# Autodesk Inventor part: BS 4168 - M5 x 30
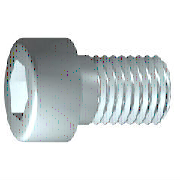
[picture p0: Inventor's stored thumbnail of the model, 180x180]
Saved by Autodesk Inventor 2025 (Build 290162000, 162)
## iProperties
Created: 2024-01
Part Number: BS 4168 - M5 x 30
Material: Acciaio, Dolce
Description: Vite con esagono incassato
Document SubType Name: Modeling
Standard: BS 4168
Designer: R5800u
Standards Organization: BSI
Language: it-IT
Size Designation: M5 x 30
Categories: <MemberInstance><Categories><Category DisplayName="Elementi di fissaggio" InternalName="e4da775c-781d-43d5-af7c-5136215cf5a6" Mnemonic="FSTN"><Category DisplayN
Density: 7.85 g/cm^3
Appearance: Semilucidato
IsCustomPart: 0
Author: R5800u
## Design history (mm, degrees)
workplane "Work Plane1"
fillet "Fillet2" dims "d30" = 0.1 (= R)
revolve "Corpo" stored, may be unused: angle "d10" = 90 deg
sketch "Schizzo2"
  geometry: L1 (0, -5.95)-(0, 5.95) reference; L2 (-5.95, 0)-(5.95, 0) reference; L3 (2.309, 0)-(1.155, -2); L4 (1.155, -2)-(-1.155, -2); L5 (-1.155, -2)-(-2.309, 0); L6 (-2.309, 0)-(-1.155, 2); L7 (-1.155, 2)-(1.155, 2); L8 (1.155, 2)-(2.309, 0); 2 further points
  constraints: 12 end point, 1 coincident, 1 horizontal alignment, 1 point on line, 12 other
extrude "Intaglio" join sketch "Schizzo2" stored distance "d11" = 10; taper "d12" = 0 deg
body "Solid1"
fillet "Raccordo1" dims "d17" = 0.5 (= RR)
feature "Filettatura" dims "d13" = 22 (= GEL), "d14" = 0
chamfer "Smusso1" distance "d15" = 0.49076 (= -0.5 x SPD + 0.5 x GD); stored, may be unused: second distance "d16" = 0.49076 (= GUL), angle "d27" = 45 deg
sketch "Schizzo1"
  geometry: L1 (-1.167, 0)-(30, 0); L2 (30, 0)-(30, 2.5); L3 (30, 2.5)-(8, 2.5); L4 (8, 2.5)-(7.509, 2.5); L5 (7.509, 2.5)-(0, 2.5); L6 (0, 2.5)-(0, 4.25); L7 (0, 4.25)-(-5, 4.25); L8 (-5, 4.25)-(-5, 2.309); L9 (-5, 2.309)-(-2.5, 2.309); L10 (-2.5, 2.309)-(-1.167, 0); L11 (-12, 0)-(37, 0) reference; L12 (0, -0.85)-(0, 5.1) reference; L13 (8, 2.5)-(0, 2.5)
  constraints: 22 end point, 6 parallel, 2 collinear, 2 perpendicular, 1 horizontal, 1 point on line
  dimensions: "d1" = 22 distance from line of L3.end L2 (= GEL); "d2" = 0.49086 distance of L4.end L3.end (computed from GAL); "d3" = 5 distance between parallel lines of L8 L6 (= KOH); "d4" = 2.5 distance of L8.end L9.end (= INTI); "d5" = 60 deg angle of L10 L1; "d6" = 5 diameter of L3 L1 (= GD); "d7" = 5 diameter of L5 L1 (= BDM); "d8" = 4.6188 diameter of L9 L1 (= 1.1547 x SW); "d9" = 8.5 diameter of L7 L1 (= KOD); "d26" = 30 distance between parallel lines of L12 L2 (= NLG)
other parameters: "GD" = 5 (= NND) [user parameter; used in 2 equation terms], "NLG" = 30 [user parameter; used in 1 equation term], "GEL" = 22 [user parameter; used in 2 equation terms], "KOD" = 8.5 [user parameter; used in 1 equation term], "KOH" = 5 (= NND) [user parameter; used in 1 equation term], "INTI" = 2.5 [user parameter; used in 1 equation term], "GAL" = 0.49076 (= 0.61345 x PTC) [user parameter; used in 1 equation term], "GUL" = 0.49076 (= 0.61345 x PTC) [user parameter; used in 1 equation term], "BDM" = 5 (= NND) [user parameter; used in 1 equation term], "SW" = 4 [user parameter; used in 2 equation terms], "RR" = 0.5 (= 0.1 x NND) [user parameter; used in 1 equation term], "SPD" = 4.01848 (= NND - 1.2269 x PTC) [user parameter; used in 1 equation term], "d19" = 0, "d28" = 0, "d29" = 0, "R" = 0.1 [user parameter; used in 1 equation term], "TOA" = 30 deg [user parameter], "GD1" = 4.01848 (= THREADDIA - 1.2269 x PTC) [user parameter], "THREADDIA" = 5 [user parameter; used in 1 equation term], "FAWI" = 45 deg [user parameter], "TPU" = 12.5 (computed from PTC) [user parameter], "PTC" = 0.8 [user parameter; used in 5 equation terms], "NND" = 5 [user parameter; used in 5 equation terms], "E0" = 4.62 (= 1.155 x SW) [user parameter]
